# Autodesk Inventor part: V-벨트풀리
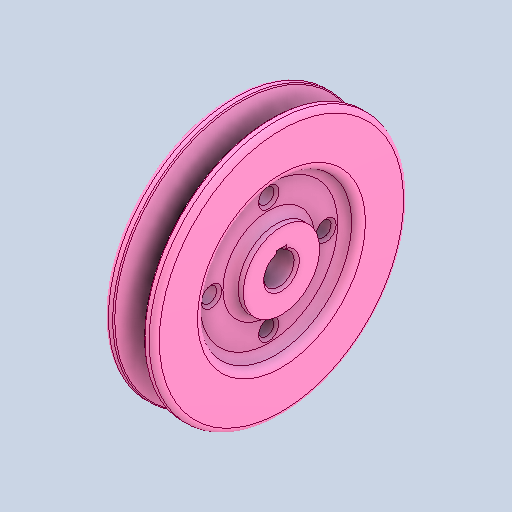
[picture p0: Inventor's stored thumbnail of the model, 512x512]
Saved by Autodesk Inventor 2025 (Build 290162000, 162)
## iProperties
Created: 2025-08
Part Number: V-벨트풀리
Material: 강철, 연강
Document SubType Name: Modeling
Designer: infra017
Density: 7.86 g/cm^3
Appearance: 기본값
Author: jhkim
Sending System: Autodesk Inventor 2026
Preprocessor: ST-DEVELOPER v20.1
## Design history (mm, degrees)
feature "솔리드1"
node "솔리드2"
